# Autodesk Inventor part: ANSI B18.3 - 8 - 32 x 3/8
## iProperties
IsCustomPart: 0
Created: 2008-02
Part Number: ANSI B18.3 - 8 - 32 x 3/8
Material: Steel, Mild
Description: Hexagon Socket Button Head Cap Screw
Document SubType Name: Modeling
Standard: ANSI B18.3
Standard Revision: 2003
Standards Organization: ANSI
Language: en-US
Size Designation: 8 - 32 x 3/8
Categories: <MemberInstance><Categories><Category DisplayName="Fasteners" InternalName="e4da775c-781d-43d5-af7c-5136215cf5a6" Mnemonic="FSTN"><Category DisplayName="Bolts"
Density: 1 g/cm^3
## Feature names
1. Body [Revolution]
2. Slot [Extrusion]
3. Fillet1
4. Chamfer1
5. Fillet2
